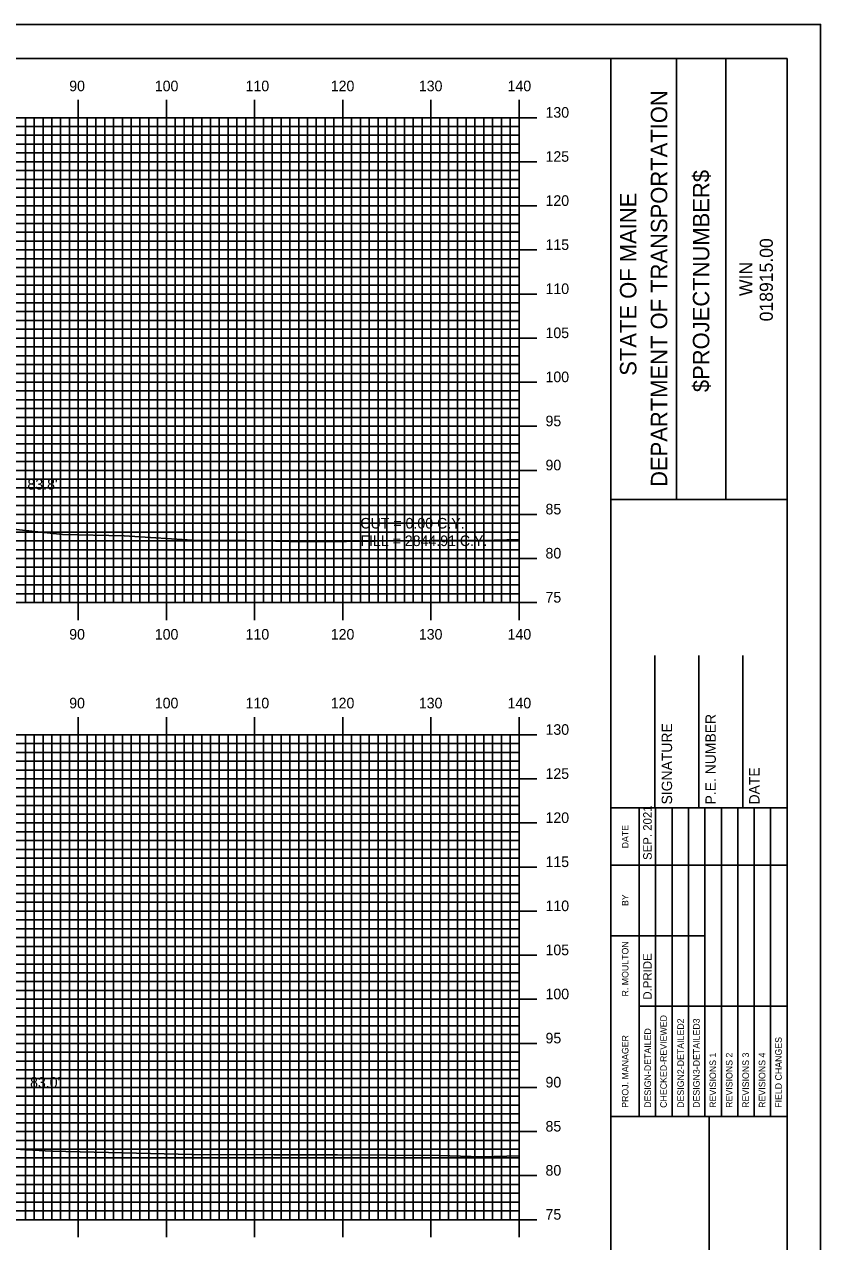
# Model space of a CAD drawing. Extents: x 856478 to 856821, y 364366 to 364586.
# Drawn here: x 856727.2 to 856817.5, y 364447.6 to 364585.7 of the extents above; entities that cross this region are included whole.
import ezdxf

# ---------------------------------------------------------------- set-up
doc = ezdxf.new("R2010")
doc.units = 0
for name, color, linetype in [('BORDER', 7, 'Continuous'), ('D_Text_Standard', 7, 'Continuous'), ('H_V ANNOTATION', 7, 'Continuous'), ('MAJOR', 7, 'Continuous'), ('MINOR', 7, 'Continuous'), ('PLOT BOUNDARY', 7, 'Continuous'), ('S_Roadway_Centerline', 7, 'Continuous')]:
    doc.layers.add(name, color=color, linetype=linetype)

msp = doc.modelspace()

# ---------------------------------------------------------------- linework, layer by layer
at = {"layer": 'BORDER'}
for p, q in [((856793.71, 364371.79), (856793.71, 364581.79)), ((856801.17, 364531.78), (856801.17, 364581.78)), ((856806.76, 364531.78), (856806.76, 364581.78)), ((856793.71, 364531.78), (856813.71, 364531.78)), ((856798.71, 364496.79), (856798.71, 364514.09)), ((856803.71, 364496.79), (856803.71, 364514.09)), ((856808.71, 364496.79), (856808.71, 364514.09)), ((856793.71, 364496.79), (856813.71, 364496.79)), ((856793.71, 364461.79), (856813.71, 364461.79)), ((856804.89, 364391.79), (856804.89, 364461.79))]:
    msp.add_line(p, q, dxfattribs=at)
msp.add_lwpolyline([(856493.71, 364371.79), (856813.71, 364371.79), (856813.71, 364581.79), (856493.71, 364581.79)], close=True, dxfattribs=at)
for points in [[(856796.94, 364490.29), (856796.94, 364496.79)], [(856798.8, 364461.8), (856798.8, 364496.79)], [(856800.67, 364496.79), (856800.67, 364461.8)], [(856802.53, 364461.8), (856802.53, 364496.79)], [(856804.39, 364461.8), (856804.39, 364496.79)], [(856806.26, 364461.8), (856806.26, 364496.79)], [(856808.12, 364461.8), (856808.12, 364496.79)], [(856809.98, 364461.8), (856809.98, 364496.79)], [(856811.85, 364461.8), (856811.85, 364496.79)], [(856796.94, 364461.8), (856796.94, 364495.38)], [(856793.71, 364490.29), (856813.71, 364490.29)], [(856793.71, 364482.29), (856796.94, 364482.29)], [(856796.94, 364482.29), (856804.39, 364482.29)], [(856796.94, 364474.29), (856813.71, 364474.29)]]:
    msp.add_lwpolyline(points, dxfattribs=at)
at = {"layer": 'MAJOR'}
for p, q in [((856733.31, 364577.09), (856733.31, 364575.08)), ((856743.31, 364577.09), (856743.31, 364575.08)), ((856753.31, 364577.09), (856753.31, 364575.08)), ((856763.31, 364577.09), (856763.31, 364575.08)), ((856773.31, 364577.09), (856773.31, 364575.08)), ((856783.31, 364577.09), (856783.31, 364575.08)), ((856503.31, 364575.08), (856783.31, 364575.08)), ((856503.31, 364575.08), (856783.31, 364575.08)), ((856733.31, 364520.08), (856733.31, 364575.08)), ((856743.31, 364520.08), (856743.31, 364575.08)), ((856753.31, 364520.08), (856753.31, 364575.08)), ((856763.31, 364520.08), (856763.31, 364575.08)), ((856773.31, 364520.08), (856773.31, 364575.08)), ((856785.31, 364575.08), (856781.31, 364575.08)), ((856783.31, 364520.08), (856783.31, 364575.08)), ((856783.31, 364520.08), (856783.31, 364575.08)), ((856503.31, 364570.08), (856783.31, 364570.08)), ((856785.31, 364570.08), (856781.31, 364570.08)), ((856503.31, 364565.08), (856783.31, 364565.08)), ((856785.31, 364565.08), (856781.31, 364565.08)), ((856503.31, 364560.08), (856783.31, 364560.08)), ((856785.31, 364560.08), (856781.31, 364560.08)), ((856503.31, 364555.08), (856783.31, 364555.08)), ((856785.31, 364555.08), (856781.31, 364555.08)), ((856503.31, 364550.08), (856783.31, 364550.08)), ((856785.31, 364550.08), (856781.31, 364550.08)), ((856503.31, 364545.08), (856783.31, 364545.08)), ((856785.31, 364545.08), (856781.31, 364545.08)), ((856503.31, 364540.08), (856783.31, 364540.08)), ((856785.31, 364540.08), (856781.31, 364540.08)), ((856503.31, 364535.08), (856783.31, 364535.08)), ((856785.31, 364535.08), (856781.31, 364535.08)), ((856503.31, 364530.08), (856783.31, 364530.08)), ((856785.31, 364530.08), (856781.31, 364530.08)), ((856503.31, 364525.08), (856783.31, 364525.08)), ((856785.31, 364525.08), (856781.31, 364525.08)), ((856503.31, 364520.08), (856783.31, 364520.08)), ((856503.31, 364520.08), (856783.31, 364520.08)), ((856733.31, 364518.08), (856733.31, 364520.08)), ((856743.31, 364518.08), (856743.31, 364520.08)), ((856753.31, 364518.08), (856753.31, 364520.08)), ((856763.31, 364518.08), (856763.31, 364520.08)), ((856773.31, 364518.08), (856773.31, 364520.08)), ((856785.31, 364520.08), (856781.31, 364520.08)), ((856783.31, 364518.08), (856783.31, 364520.08)), ((856733.31, 364507.09), (856733.31, 364505.08)), ((856743.31, 364507.09), (856743.31, 364505.08)), ((856753.31, 364507.09), (856753.31, 364505.08)), ((856763.31, 364507.09), (856763.31, 364505.08)), ((856773.31, 364507.09), (856773.31, 364505.08)), ((856783.31, 364507.09), (856783.31, 364505.08)), ((856503.31, 364505.08), (856783.31, 364505.08)), ((856503.31, 364505.08), (856783.31, 364505.08)), ((856733.31, 364450.08), (856733.31, 364505.08)), ((856743.31, 364450.08), (856743.31, 364505.08)), ((856753.31, 364450.08), (856753.31, 364505.08)), ((856763.31, 364450.08), (856763.31, 364505.08)), ((856773.31, 364450.08), (856773.31, 364505.08)), ((856785.31, 364505.08), (856781.31, 364505.08)), ((856783.31, 364450.08), (856783.31, 364505.08)), ((856783.31, 364450.08), (856783.31, 364505.08)), ((856503.31, 364500.08), (856783.31, 364500.08)), ((856785.31, 364500.08), (856781.31, 364500.08)), ((856503.31, 364495.08), (856783.31, 364495.08)), ((856785.31, 364495.08), (856781.31, 364495.08)), ((856503.31, 364490.08), (856783.31, 364490.08)), ((856785.31, 364490.08), (856781.31, 364490.08)), ((856503.31, 364485.08), (856783.31, 364485.08)), ((856785.31, 364485.08), (856781.31, 364485.08)), ((856503.31, 364480.08), (856783.31, 364480.08)), ((856785.31, 364480.08), (856781.31, 364480.08)), ((856503.31, 364475.08), (856783.31, 364475.08)), ((856785.31, 364475.08), (856781.31, 364475.08)), ((856503.31, 364470.08), (856783.31, 364470.08)), ((856785.31, 364470.08), (856781.31, 364470.08)), ((856503.31, 364465.08), (856783.31, 364465.08)), ((856785.31, 364465.08), (856781.31, 364465.08)), ((856503.31, 364460.08), (856783.31, 364460.08)), ((856785.31, 364460.08), (856781.31, 364460.08)), ((856503.31, 364455.08), (856783.31, 364455.08)), ((856785.31, 364455.08), (856781.31, 364455.08)), ((856503.31, 364450.08), (856783.31, 364450.08)), ((856503.31, 364450.08), (856783.31, 364450.08)), ((856733.31, 364448.08), (856733.31, 364450.08)), ((856743.31, 364448.08), (856743.31, 364450.08)), ((856753.31, 364448.08), (856753.31, 364450.08)), ((856763.31, 364448.08), (856763.31, 364450.08)), ((856773.31, 364448.08), (856773.31, 364450.08)), ((856785.31, 364450.08), (856781.31, 364450.08)), ((856783.31, 364448.08), (856783.31, 364450.08))]:
    msp.add_line(p, q, dxfattribs=at)
at = {"layer": 'MINOR'}
for p, q in [((856503.31, 364574.08), (856783.31, 364574.08)), ((856727.31, 364520.08), (856727.31, 364575.08)), ((856728.31, 364520.08), (856728.31, 364575.08)), ((856729.31, 364520.08), (856729.31, 364575.08)), ((856730.31, 364520.08), (856730.31, 364575.08)), ((856731.31, 364520.08), (856731.31, 364575.08)), ((856732.31, 364520.08), (856732.31, 364575.08)), ((856734.31, 364520.08), (856734.31, 364575.08)), ((856735.31, 364520.08), (856735.31, 364575.08)), ((856736.31, 364520.08), (856736.31, 364575.08)), ((856737.31, 364520.08), (856737.31, 364575.08)), ((856738.31, 364520.08), (856738.31, 364575.08)), ((856739.31, 364520.08), (856739.31, 364575.08)), ((856740.31, 364520.08), (856740.31, 364575.08)), ((856741.31, 364520.08), (856741.31, 364575.08)), ((856742.31, 364520.08), (856742.31, 364575.08)), ((856744.31, 364520.08), (856744.31, 364575.08)), ((856745.31, 364520.08), (856745.31, 364575.08)), ((856746.31, 364520.08), (856746.31, 364575.08)), ((856747.31, 364520.08), (856747.31, 364575.08)), ((856748.31, 364520.08), (856748.31, 364575.08)), ((856749.31, 364520.08), (856749.31, 364575.08)), ((856750.31, 364520.08), (856750.31, 364575.08)), ((856751.31, 364520.08), (856751.31, 364575.08)), ((856752.31, 364520.08), (856752.31, 364575.08)), ((856754.31, 364520.08), (856754.31, 364575.08)), ((856755.31, 364520.08), (856755.31, 364575.08)), ((856756.31, 364520.08), (856756.31, 364575.08)), ((856757.31, 364520.08), (856757.31, 364575.08)), ((856758.31, 364520.08), (856758.31, 364575.08)), ((856759.31, 364520.08), (856759.31, 364575.08)), ((856760.31, 364520.08), (856760.31, 364575.08)), ((856761.31, 364520.08), (856761.31, 364575.08)), ((856762.31, 364520.08), (856762.31, 364575.08)), ((856764.31, 364520.08), (856764.31, 364575.08)), ((856765.31, 364520.08), (856765.31, 364575.08)), ((856766.31, 364520.08), (856766.31, 364575.08)), ((856767.31, 364520.08), (856767.31, 364575.08)), ((856768.31, 364520.08), (856768.31, 364575.08)), ((856769.31, 364520.08), (856769.31, 364575.08)), ((856770.31, 364520.08), (856770.31, 364575.08)), ((856771.31, 364520.08), (856771.31, 364575.08)), ((856772.31, 364520.08), (856772.31, 364575.08)), ((856774.31, 364520.08), (856774.31, 364575.08)), ((856775.31, 364520.08), (856775.31, 364575.08)), ((856776.31, 364520.08), (856776.31, 364575.08)), ((856777.31, 364520.08), (856777.31, 364575.08)), ((856778.31, 364520.08), (856778.31, 364575.08)), ((856779.31, 364520.08), (856779.31, 364575.08)), ((856780.31, 364520.08), (856780.31, 364575.08)), ((856781.31, 364520.08), (856781.31, 364575.08)), ((856783.31, 364574.08), (856781.31, 364574.08)), ((856782.31, 364520.08), (856782.31, 364575.08)), ((856503.31, 364573.08), (856783.31, 364573.08)), ((856783.31, 364573.08), (856781.31, 364573.08)), ((856503.31, 364572.08), (856783.31, 364572.08)), ((856783.31, 364572.08), (856781.31, 364572.08)), ((856503.31, 364571.08), (856783.31, 364571.08)), ((856783.31, 364571.08), (856781.31, 364571.08)), ((856503.31, 364569.08), (856783.31, 364569.08)), ((856783.31, 364569.08), (856781.31, 364569.08)), ((856503.31, 364568.08), (856783.31, 364568.08)), ((856783.31, 364568.08), (856781.31, 364568.08)), ((856503.31, 364567.08), (856783.31, 364567.08)), ((856503.31, 364566.08), (856783.31, 364566.08)), ((856783.31, 364567.08), (856781.31, 364567.08)), ((856783.31, 364566.08), (856781.31, 364566.08)), ((856503.31, 364564.08), (856783.31, 364564.08)), ((856503.31, 364563.08), (856783.31, 364563.08)), ((856783.31, 364564.08), (856781.31, 364564.08)), ((856783.31, 364563.08), (856781.31, 364563.08)), ((856503.31, 364562.08), (856783.31, 364562.08)), ((856783.31, 364562.08), (856781.31, 364562.08)), ((856503.31, 364561.08), (856783.31, 364561.08)), ((856783.31, 364561.08), (856781.31, 364561.08)), ((856503.31, 364559.08), (856783.31, 364559.08)), ((856783.31, 364559.08), (856781.31, 364559.08)), ((856503.31, 364558.08), (856783.31, 364558.08)), ((856783.31, 364558.08), (856781.31, 364558.08)), ((856503.31, 364557.08), (856783.31, 364557.08)), ((856783.31, 364557.08), (856781.31, 364557.08)), ((856503.31, 364556.08), (856783.31, 364556.08)), ((856783.31, 364556.08), (856781.31, 364556.08)), ((856503.31, 364554.08), (856783.31, 364554.08)), ((856783.31, 364554.08), (856781.31, 364554.08)), ((856503.31, 364553.08), (856783.31, 364553.08)), ((856503.31, 364552.08), (856783.31, 364552.08)), ((856783.31, 364553.08), (856781.31, 364553.08)), ((856783.31, 364552.08), (856781.31, 364552.08)), ((856503.31, 364551.08), (856783.31, 364551.08)), ((856783.31, 364551.08), (856781.31, 364551.08)), ((856503.31, 364549.08), (856783.31, 364549.08)), ((856503.31, 364548.08), (856783.31, 364548.08)), ((856783.31, 364549.08), (856781.31, 364549.08)), ((856783.31, 364548.08), (856781.31, 364548.08)), ((856503.31, 364547.08), (856783.31, 364547.08)), ((856783.31, 364547.08), (856781.31, 364547.08)), ((856503.31, 364546.08), (856783.31, 364546.08)), ((856783.31, 364546.08), (856781.31, 364546.08)), ((856503.31, 364544.08), (856783.31, 364544.08)), ((856783.31, 364544.08), (856781.31, 364544.08)), ((856503.31, 364543.08), (856783.31, 364543.08)), ((856783.31, 364543.08), (856781.31, 364543.08)), ((856503.31, 364542.08), (856783.31, 364542.08)), ((856503.31, 364541.08), (856783.31, 364541.08)), ((856783.31, 364542.08), (856781.31, 364542.08)), ((856783.31, 364541.08), (856781.31, 364541.08)), ((856503.31, 364539.08), (856783.31, 364539.08)), ((856783.31, 364539.08), (856781.31, 364539.08)), ((856503.31, 364538.08), (856783.31, 364538.08)), ((856503.31, 364537.08), (856783.31, 364537.08)), ((856783.31, 364538.08), (856781.31, 364538.08)), ((856783.31, 364537.08), (856781.31, 364537.08)), ((856503.31, 364536.08), (856783.31, 364536.08)), ((856783.31, 364536.08), (856781.31, 364536.08)), ((856503.31, 364534.08), (856783.31, 364534.08)), ((856783.31, 364534.08), (856781.31, 364534.08)), ((856503.31, 364533.08), (856783.31, 364533.08)), ((856783.31, 364533.08), (856781.31, 364533.08)), ((856503.31, 364532.08), (856783.31, 364532.08)), ((856783.31, 364532.08), (856781.31, 364532.08)), ((856503.31, 364531.08), (856783.31, 364531.08)), ((856783.31, 364531.08), (856781.31, 364531.08)), ((856503.31, 364529.08), (856783.31, 364529.08)), ((856783.31, 364529.08), (856781.31, 364529.08)), ((856503.31, 364528.08), (856783.31, 364528.08)), ((856783.31, 364528.08), (856781.31, 364528.08)), ((856503.31, 364527.08), (856783.31, 364527.08)), ((856503.31, 364526.08), (856783.31, 364526.08)), ((856783.31, 364527.08), (856781.31, 364527.08)), ((856783.31, 364526.08), (856781.31, 364526.08)), ((856503.31, 364524.08), (856783.31, 364524.08)), ((856503.31, 364523.08), (856783.31, 364523.08)), ((856783.31, 364524.08), (856781.31, 364524.08)), ((856783.31, 364523.08), (856781.31, 364523.08)), ((856503.31, 364522.08), (856783.31, 364522.08)), ((856783.31, 364522.08), (856781.31, 364522.08)), ((856503.31, 364521.08), (856783.31, 364521.08)), ((856783.31, 364521.08), (856781.31, 364521.08)), ((856727.31, 364450.08), (856727.31, 364505.08)), ((856728.31, 364450.08), (856728.31, 364505.08)), ((856729.31, 364450.08), (856729.31, 364505.08)), ((856730.31, 364450.08), (856730.31, 364505.08)), ((856731.31, 364450.08), (856731.31, 364505.08)), ((856732.31, 364450.08), (856732.31, 364505.08)), ((856734.31, 364450.08), (856734.31, 364505.08)), ((856735.31, 364450.08), (856735.31, 364505.08)), ((856736.31, 364450.08), (856736.31, 364505.08)), ((856737.31, 364450.08), (856737.31, 364505.08)), ((856738.31, 364450.08), (856738.31, 364505.08)), ((856739.31, 364450.08), (856739.31, 364505.08)), ((856740.31, 364450.08), (856740.31, 364505.08)), ((856741.31, 364450.08), (856741.31, 364505.08)), ((856742.31, 364450.08), (856742.31, 364505.08)), ((856744.31, 364450.08), (856744.31, 364505.08)), ((856745.31, 364450.08), (856745.31, 364505.08)), ((856746.31, 364450.08), (856746.31, 364505.08)), ((856747.31, 364450.08), (856747.31, 364505.08)), ((856748.31, 364450.08), (856748.31, 364505.08)), ((856749.31, 364450.08), (856749.31, 364505.08)), ((856750.31, 364450.08), (856750.31, 364505.08)), ((856751.31, 364450.08), (856751.31, 364505.08)), ((856752.31, 364450.08), (856752.31, 364505.08)), ((856754.31, 364450.08), (856754.31, 364505.08)), ((856755.31, 364450.08), (856755.31, 364505.08)), ((856756.31, 364450.08), (856756.31, 364505.08)), ((856757.31, 364450.08), (856757.31, 364505.08)), ((856758.31, 364450.08), (856758.31, 364505.08)), ((856759.31, 364450.08), (856759.31, 364505.08)), ((856760.31, 364450.08), (856760.31, 364505.08)), ((856761.31, 364450.08), (856761.31, 364505.08)), ((856762.31, 364450.08), (856762.31, 364505.08)), ((856764.31, 364450.08), (856764.31, 364505.08)), ((856765.31, 364450.08), (856765.31, 364505.08)), ((856766.31, 364450.08), (856766.31, 364505.08)), ((856767.31, 364450.08), (856767.31, 364505.08)), ((856768.31, 364450.08), (856768.31, 364505.08)), ((856769.31, 364450.08), (856769.31, 364505.08)), ((856770.31, 364450.08), (856770.31, 364505.08)), ((856771.31, 364450.08), (856771.31, 364505.08)), ((856772.31, 364450.08), (856772.31, 364505.08)), ((856774.31, 364450.08), (856774.31, 364505.08)), ((856775.31, 364450.08), (856775.31, 364505.08)), ((856776.31, 364450.08), (856776.31, 364505.08)), ((856777.31, 364450.08), (856777.31, 364505.08)), ((856778.31, 364450.08), (856778.31, 364505.08)), ((856779.31, 364450.08), (856779.31, 364505.08)), ((856780.31, 364450.08), (856780.31, 364505.08)), ((856781.31, 364450.08), (856781.31, 364505.08)), ((856782.31, 364450.08), (856782.31, 364505.08)), ((856503.31, 364504.08), (856783.31, 364504.08)), ((856783.31, 364504.08), (856781.31, 364504.08)), ((856503.31, 364503.08), (856783.31, 364503.08)), ((856783.31, 364503.08), (856781.31, 364503.08)), ((856503.31, 364502.08), (856783.31, 364502.08)), ((856503.31, 364501.08), (856783.31, 364501.08)), ((856783.31, 364502.08), (856781.31, 364502.08)), ((856783.31, 364501.08), (856781.31, 364501.08)), ((856503.31, 364499.08), (856783.31, 364499.08)), ((856783.31, 364499.08), (856781.31, 364499.08)), ((856503.31, 364498.08), (856783.31, 364498.08)), ((856503.31, 364497.08), (856783.31, 364497.08)), ((856783.31, 364498.08), (856781.31, 364498.08)), ((856783.31, 364497.08), (856781.31, 364497.08)), ((856503.31, 364496.08), (856783.31, 364496.08)), ((856783.31, 364496.08), (856781.31, 364496.08)), ((856503.31, 364494.08), (856783.31, 364494.08)), ((856783.31, 364494.08), (856781.31, 364494.08)), ((856503.31, 364493.08), (856783.31, 364493.08)), ((856783.31, 364493.08), (856781.31, 364493.08)), ((856503.31, 364492.08), (856783.31, 364492.08)), ((856783.31, 364492.08), (856781.31, 364492.08)), ((856503.31, 364491.08), (856783.31, 364491.08)), ((856783.31, 364491.08), (856781.31, 364491.08)), ((856503.31, 364489.08), (856783.31, 364489.08)), ((856783.31, 364489.08), (856781.31, 364489.08)), ((856503.31, 364488.08), (856783.31, 364488.08)), ((856503.31, 364487.08), (856783.31, 364487.08)), ((856783.31, 364488.08), (856781.31, 364488.08)), ((856783.31, 364487.08), (856781.31, 364487.08)), ((856503.31, 364486.08), (856783.31, 364486.08)), ((856783.31, 364486.08), (856781.31, 364486.08)), ((856503.31, 364484.08), (856783.31, 364484.08)), ((856503.31, 364483.08), (856783.31, 364483.08)), ((856783.31, 364484.08), (856781.31, 364484.08)), ((856783.31, 364483.08), (856781.31, 364483.08)), ((856503.31, 364482.08), (856783.31, 364482.08)), ((856783.31, 364482.08), (856781.31, 364482.08)), ((856503.31, 364481.08), (856783.31, 364481.08)), ((856783.31, 364481.08), (856781.31, 364481.08)), ((856503.31, 364479.08), (856783.31, 364479.08)), ((856783.31, 364479.08), (856781.31, 364479.08)), ((856503.31, 364478.08), (856783.31, 364478.08)), ((856783.31, 364478.08), (856781.31, 364478.08)), ((856503.31, 364477.08), (856783.31, 364477.08)), ((856503.31, 364476.08), (856783.31, 364476.08)), ((856783.31, 364477.08), (856781.31, 364477.08)), ((856783.31, 364476.08), (856781.31, 364476.08)), ((856503.31, 364474.08), (856783.31, 364474.08)), ((856783.31, 364474.08), (856781.31, 364474.08)), ((856503.31, 364473.08), (856783.31, 364473.08)), ((856503.31, 364472.08), (856783.31, 364472.08)), ((856783.31, 364473.08), (856781.31, 364473.08)), ((856783.31, 364472.08), (856781.31, 364472.08)), ((856503.31, 364471.08), (856783.31, 364471.08)), ((856783.31, 364471.08), (856781.31, 364471.08)), ((856503.31, 364469.08), (856783.31, 364469.08)), ((856503.31, 364468.08), (856783.31, 364468.08)), ((856783.31, 364469.08), (856781.31, 364469.08)), ((856783.31, 364468.08), (856781.31, 364468.08)), ((856503.31, 364467.08), (856783.31, 364467.08)), ((856783.31, 364467.08), (856781.31, 364467.08)), ((856503.31, 364466.08), (856783.31, 364466.08)), ((856783.31, 364466.08), (856781.31, 364466.08)), ((856503.31, 364464.08), (856783.31, 364464.08)), ((856783.31, 364464.08), (856781.31, 364464.08)), ((856503.31, 364463.08), (856783.31, 364463.08)), ((856783.31, 364463.08), (856781.31, 364463.08)), ((856503.31, 364462.08), (856783.31, 364462.08)), ((856503.31, 364461.08), (856783.31, 364461.08)), ((856783.31, 364462.08), (856781.31, 364462.08)), ((856783.31, 364461.08), (856781.31, 364461.08)), ((856503.31, 364459.08), (856783.31, 364459.08)), ((856503.31, 364458.08), (856783.31, 364458.08)), ((856783.31, 364459.08), (856781.31, 364459.08)), ((856783.31, 364458.08), (856781.31, 364458.08)), ((856503.31, 364457.08), (856783.31, 364457.08)), ((856783.31, 364457.08), (856781.31, 364457.08)), ((856503.31, 364456.08), (856783.31, 364456.08)), ((856783.31, 364456.08), (856781.31, 364456.08)), ((856503.31, 364454.08), (856783.31, 364454.08)), ((856783.31, 364454.08), (856781.31, 364454.08)), ((856503.31, 364453.08), (856783.31, 364453.08)), ((856783.31, 364453.08), (856781.31, 364453.08)), ((856503.31, 364452.08), (856783.31, 364452.08)), ((856503.31, 364451.08), (856783.31, 364451.08)), ((856783.31, 364451.08), (856781.31, 364451.08))]:
    msp.add_line(p, q, dxfattribs=at)
at = {"layer": 'PLOT BOUNDARY'}
msp.add_lwpolyline([(856477.52, 364365.67), (856817.52, 364365.67), (856817.52, 364585.67), (856477.52, 364585.67)], close=True, dxfattribs=at)
at = {"layer": 'S_Roadway_Centerline'}
for points in [[(856600.75, 364549.07), (856609.18, 364547.9), (856616.41, 364545.87), (856624.97, 364545.49), (856632.8, 364545.27), (856641.36, 364544.87), (856649.52, 364544.46), (856657.83, 364542.58), (856674.51, 364539.19), (856689.71, 364535.01), (856707.33, 364530.44), (856714.43, 364529.03), (856722.05, 364528.83), (856731.51, 364527.81), (856738.52, 364527.64), (856746.86, 364527.14), (856752.42, 364527.12), (856757.29, 364526.99), (856763.74, 364526.99), (856773.12, 364527.14), (856779.07, 364527.12), (856783.31, 364527.24)], [(856603.11, 364476.01), (856615.61, 364475.07), (856617.72, 364474.96), (856631.47, 364473.99), (856644.99, 364472.19), (856648.12, 364471.87), (856663.52, 364468.1), (856664.96, 364467.79), (856678.41, 364463.96), (856685.01, 364462.25), (856697.73, 364459.66), (856702.22, 364458.81), (856713.93, 364458.58), (856720.37, 364458.39), (856730.27, 364457.84), (856738.35, 364457.68), (856746.19, 364457.47), (856755.54, 364457.45), (856762.71, 364457.43), (856774.23, 364457.36), (856779.08, 364457.22), (856783.31, 364457.33)]]:
    msp.add_lwpolyline(points, dxfattribs=at)

# ---------------------------------------------------------------- texts
at = {"layer": 'BORDER'}
for s, height, p in [('DEPARTMENT OF TRANSPORTATION', 1.8635, (856800.12, 364533.2)), ('$PROJECTNUMBER$', 1.8635, (856804.89, 364543.95)), ('STATE OF MAINE', 1.8635, (856796.62, 364545.81)), ('018915.00', 1.491, (856812.1, 364551.98)), ('WIN', 1.491, (856809.78, 364554.85)), ('P.E. NUMBER', 1.1811, (856805.63, 364497.18)), ('SIGNATURE', 1.181, (856800.67, 364497.18)), ('DATE', 1.181, (856810.59, 364497.18)), ('SEP. 2021', 0.969, (856798.36, 364490.88)), ('DATE', 0.743, (856795.72, 364492.2)), ('BY', 0.743, (856795.72, 364485.66)), ('R. MOULTON', 0.745, (856795.72, 364475.4)), ('D.PRIDE', 0.969, (856798.36, 364475.04)), ('CHECKED-REVIEWED', 0.7455, (856800.07, 364462.77)), ('DESIGN2-DETAILED2', 0.7455, (856802.01, 364462.77)), ('DESIGN3-DETAILED3', 0.7455, (856803.8, 364462.77)), ('PROJ. MANAGER', 0.7455, (856795.72, 364462.77)), ('DESIGN-DETAILED', 0.7455, (856798.28, 364462.77)), ('FIELD CHANGES', 0.7455, (856813.11, 364462.77)), ('REVISIONS 1', 0.7455, (856805.66, 364462.77)), ('REVISIONS 2', 0.7455, (856807.52, 364462.77)), ('REVISIONS 3', 0.7455, (856809.39, 364462.77)), ('REVISIONS 4', 0.7455, (856811.25, 364462.77))]:
    msp.add_text(s, height=height, rotation=90, dxfattribs=at).set_placement(p)
at = {"layer": 'D_Text_Standard'}
for s, p in [("83.8'", (856727.54, 364532.9)), ('CUT = 0.00 C.Y.', (856765.31, 364528.48)), ('FILL = 2844.91 C.Y.', (856765.31, 364526.49)), ("83.0'", (856727.84, 364465.05))]:
    msp.add_text(s, height=1.2, dxfattribs=at).set_placement(p)
at = {"layer": 'H_V ANNOTATION'}
for s, p in [('90', (856732.28, 364578.08)), ('100', (856741.99, 364578.08)), ('110', (856752.29, 364578.08)), ('120', (856761.95, 364578.08)), ('130', (856771.94, 364578.08)), ('140', (856782.01, 364578.08)), ('130', (856786.31, 364575.08)), ('125', (856786.31, 364570.08)), ('120', (856786.31, 364565.08)), ('115', (856786.31, 364560.08)), ('110', (856786.31, 364555.08)), ('105', (856786.31, 364550.08)), ('100', (856786.31, 364545.08)), ('95', (856786.31, 364540.08)), ('90', (856786.31, 364535.08)), ('85', (856786.31, 364530.08)), ('80', (856786.31, 364525.08)), ('75', (856786.31, 364520.08)), ('90', (856732.28, 364515.88)), ('100', (856741.99, 364515.88)), ('110', (856752.29, 364515.88)), ('120', (856761.95, 364515.88)), ('130', (856771.94, 364515.88)), ('140', (856782.01, 364515.88)), ('90', (856732.28, 364508.08)), ('100', (856741.99, 364508.08)), ('110', (856752.29, 364508.08)), ('120', (856761.95, 364508.08)), ('130', (856771.94, 364508.08)), ('140', (856782.01, 364508.08)), ('130', (856786.31, 364505.08)), ('125', (856786.31, 364500.08)), ('120', (856786.31, 364495.08)), ('115', (856786.31, 364490.08)), ('110', (856786.31, 364485.08)), ('105', (856786.31, 364480.08)), ('100', (856786.31, 364475.08)), ('95', (856786.31, 364470.08)), ('90', (856786.31, 364465.08)), ('85', (856786.31, 364460.08)), ('80', (856786.31, 364455.08)), ('75', (856786.31, 364450.08))]:
    msp.add_text(s, height=1.2, dxfattribs=at).set_placement(p)

doc.saveas('drawing.dxf')
